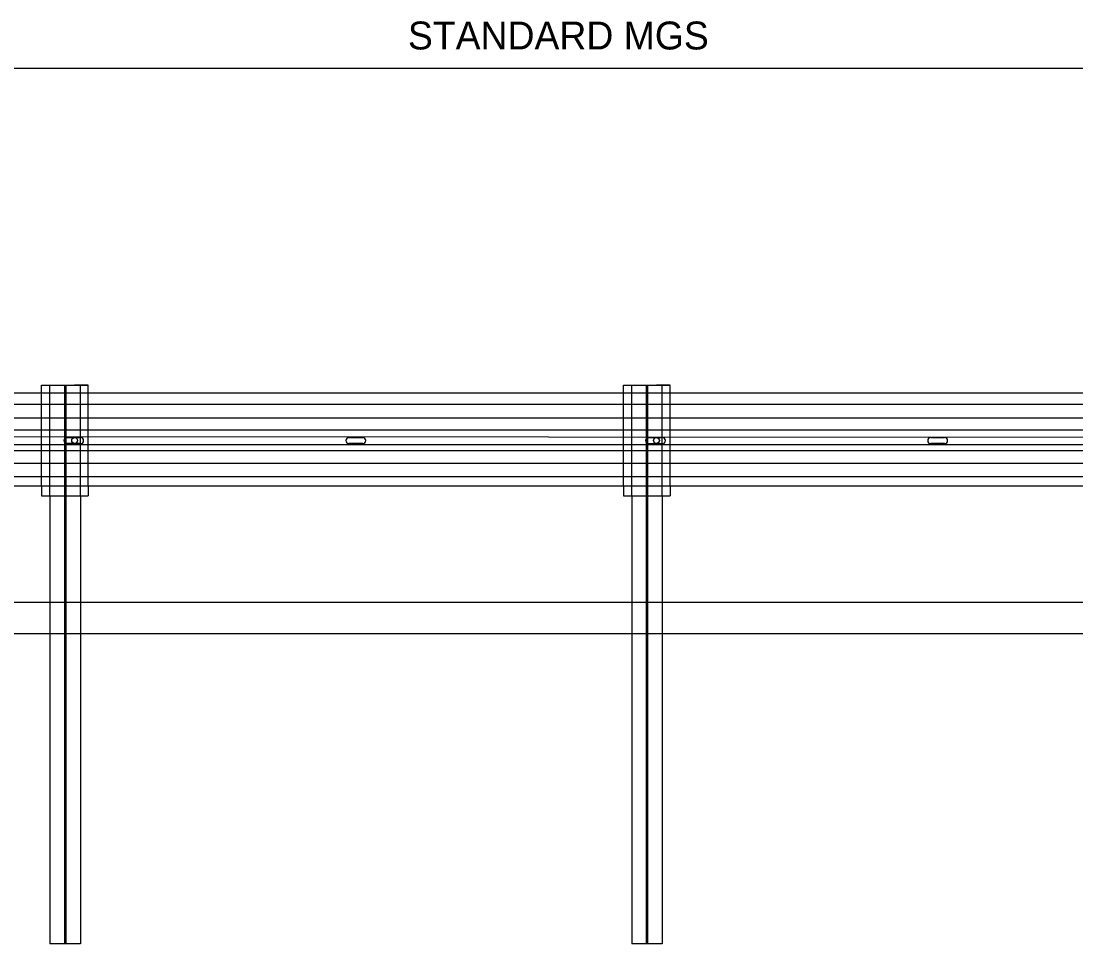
# Model space of a CAD drawing. Extents: x 49991 to 50160, y 49948 to 50051.
# Drawn here: x 50008.707 to 50010.973, y 49994.318 to 49996.3 of the extents above; entities that cross this region are included whole.
import ezdxf

# ---------------------------------------------------------------- set-up
doc = ezdxf.new("R2010")
doc.units = 0
for name, color, linetype in [('Level 1', 7, 'Continuous'), ('Level 2', 7, 'Continuous'), ('Level 3', 7, 'Continuous'), ('Level 4', 7, 'Continuous')]:
    doc.layers.add(name, color=color, linetype=linetype)

msp = doc.modelspace()

# ---------------------------------------------------------------- linework, layer by layer
at = {"layer": 'Level 1'}
for p, q in [((50008.7508, 49995.5183), (50008.8508, 49995.5183)), ((50008.7508, 49995.5017), (50008.7508, 49995.5183)), ((50008.7685, 49995.5183), (50008.8341, 49995.5183)), ((50008.8508, 49995.5183), (50008.8216, 49995.5183)), ((50008.8508, 49995.5017), (50008.8508, 49995.5183)), ((50010.0008, 49995.5183), (50010.1008, 49995.5183)), ((50010.0008, 49995.5016), (50010.0008, 49995.5183)), ((50010.0185, 49995.5183), (50010.0841, 49995.5183)), ((50010.1008, 49995.5183), (50010.0716, 49995.5183)), ((50010.1008, 49995.5016), (50010.1008, 49995.5183)), ((50004.3866, 49995.502), (50011.6716, 49995.5015)), ((50004.5497, 49995.4777), (50011.6716, 49995.4777)), ((50004.5497, 49995.4486), (50011.6716, 49995.448)), ((50004.5497, 49995.4215), (50011.6716, 49995.4225)), ((50005.0854, 49995.409), (50011.6716, 49995.4068)), ((50008.8049, 49995.4059), (50008.8345, 49995.4059)), ((50008.8345, 49995.3928), (50008.8049, 49995.3928)), ((50009.411, 49995.406), (50009.4406, 49995.406)), ((50009.4406, 49995.3929), (50009.411, 49995.3929)), ((50010.0549, 49995.4058), (50010.0845, 49995.4058)), ((50010.0845, 49995.3927), (50010.0549, 49995.3927)), ((50010.661, 49995.406), (50010.6906, 49995.406)), ((50010.6906, 49995.3929), (50010.661, 49995.3929)), ((50011.6716, 49995.3902), (50005.5897, 49995.3903)), ((50011.6716, 49995.3773), (50005.5897, 49995.3773)), ((50011.6716, 49995.3504), (50005.5897, 49995.3504)), ((50011.6716, 49995.3214), (50005.5897, 49995.3214)), ((50011.6716, 49995.3012), (50005.5897, 49995.3012)), ((50008.7508, 49995.3012), (50008.7508, 49995.2808)), ((50008.8508, 49995.3012), (50008.8508, 49995.2808)), ((50010.0008, 49995.3012), (50010.0008, 49995.2808)), ((50010.1008, 49995.3012), (50010.1008, 49995.2808)), ((50008.7508, 49995.2808), (50008.8508, 49995.2808)), ((50008.7685, 49995.2808), (50008.7685, 49995.0516)), ((50008.8341, 49995.2808), (50008.8341, 49995.0516)), ((50010.0008, 49995.2808), (50010.1008, 49995.2808)), ((50010.0185, 49995.2808), (50010.0185, 49995.0516)), ((50010.0841, 49995.2808), (50010.0841, 49995.0516)), ((50011.6716, 49995.0515), (50000.8175, 49995.052)), ((49999.8238, 49994.9854), (50011.6716, 49994.9849))]:
    msp.add_line(p, q, dxfattribs=at)
for centre in [(50008.8216, 49995.3996), (50008.8216, 49995.3996), (50010.0716, 49995.3995)]:
    msp.add_circle(centre, 0.00625, dxfattribs=at)
for centre, start, end in [((50008.8049, 49995.3993), 90, 270), ((50008.8345, 49995.3993), 270, 90), ((50009.411, 49995.3994), 90, 270), ((50009.4406, 49995.3994), 270, 90), ((50010.0549, 49995.3993), 90, 270), ((50010.0845, 49995.3993), 270, 90), ((50010.661, 49995.3994), 90, 270), ((50010.6906, 49995.3994), 270, 90)]:
    msp.add_arc(centre, 0.00656, start, end, dxfattribs=at)
at = {"layer": 'Level 3'}
msp.add_line((50008.1966, 49996.1994), (50011.5729, 49996.1994), dxfattribs=at)
at = {"layer": 'Level 4'}
for p, q in [((50008.7685, 49995.2808), (50008.7685, 49995.5183)), ((50008.7999, 49995.5183), (50008.7999, 49994.3183)), ((50008.8027, 49995.5183), (50008.8027, 49994.3183)), ((50008.8341, 49995.2808), (50008.8341, 49995.5183)), ((50010.0185, 49995.2808), (50010.0185, 49995.5183)), ((50010.0499, 49995.5183), (50010.0499, 49994.3183)), ((50010.0527, 49995.5183), (50010.0527, 49994.3183)), ((50010.0841, 49995.2808), (50010.0841, 49995.5183)), ((50008.7508, 49995.3012), (50008.7508, 49995.5017)), ((50008.8508, 49995.3012), (50008.8508, 49995.5017)), ((50010.0008, 49995.3012), (50010.0008, 49995.5016)), ((50010.1008, 49995.3012), (50010.1008, 49995.5016)), ((50008.7685, 49995.0516), (50008.7685, 49994.3183)), ((50008.8341, 49995.0516), (50008.8341, 49994.3183)), ((50010.0185, 49995.0516), (50010.0185, 49994.3183)), ((50010.0841, 49995.0516), (50010.0841, 49994.3183)), ((50008.8341, 49994.3183), (50008.7685, 49994.3183)), ((50010.0841, 49994.3183), (50010.0185, 49994.3183))]:
    msp.add_line(p, q, dxfattribs=at)

# ---------------------------------------------------------------- texts
at = {"layer": 'Level 2'}
msp.add_text('STANDARD MGS', height=0.06, dxfattribs=at).set_placement((50009.5377, 49996.2394))

doc.saveas('drawing.dxf')
